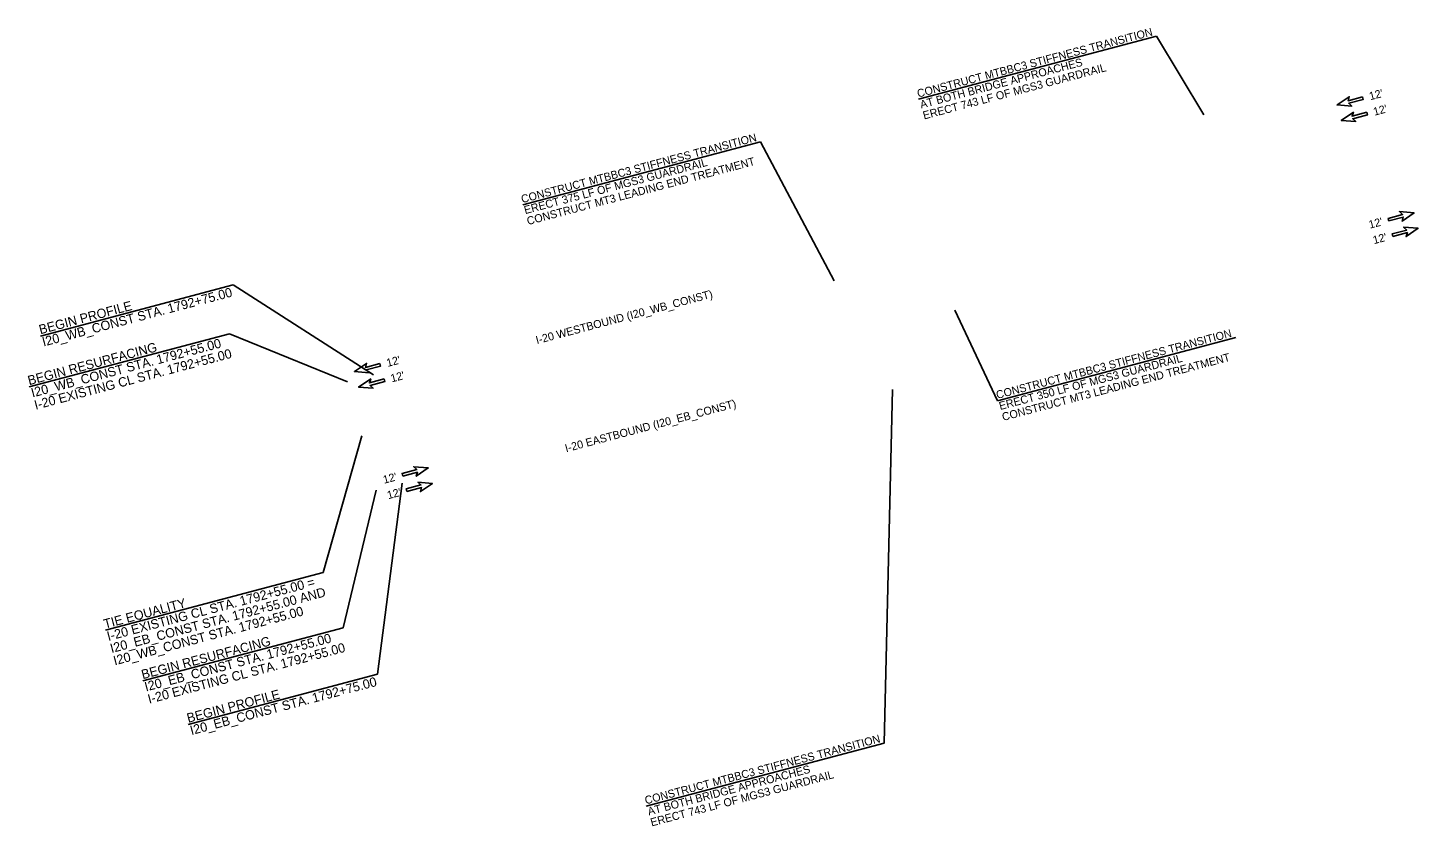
# Model space of a CAD drawing. Extents: x 2110155 to 2114862, y 866944 to 868497.
# Drawn here: x 2110155 to 2111197, y 866944 to 867543 of the extents above; entities that cross this region are included whole.
import ezdxf

# ---------------------------------------------------------------- set-up
doc = ezdxf.new("R2010")
doc.units = 0
doc.layers.add('RD_SHT_Bndy', color=7, linetype='Continuous')

msp = doc.modelspace()

# ---------------------------------------------------------------- linework, layer by layer
at = {"layer": 'RD_SHT_Bndy'}
for p, q in [((2111001.2, 867536.4), (2110822.8, 867489.1)), ((2110704.3, 867457.2), (2110525.9, 867409.9)), ((2110308.7, 867349.8), (2110164.2, 867311.5)), ((2110306, 867313.1), (2110155.8, 867273.3)), ((2111060.7, 867310.4), (2110882, 867263)), ((2110376.3, 867134.1), (2110213.1, 867090.8)), ((2110391.2, 867092.6), (2110241, 867052.8)), ((2110417.1, 867057.8), (2110275.1, 867020.1)), ((2110797, 867006.2), (2110618.6, 866959))]:
    msp.add_line(p, q, dxfattribs=at)
for points in [[(2111001.2, 867536.4), (2111036.6, 867477.4)], [(2110704.3, 867457.2), (2110759.4, 867352.8)], [(2110308.7, 867349.8), (2110413.9, 867282.4)], [(2110882, 867263), (2110849.9, 867331)], [(2110306, 867313.1), (2110394.5, 867277.2)], [(2110797, 867006.2), (2110803.2, 867271.4)], [(2110376.3, 867134.1), (2110405.3, 867236.6)], [(2110391.2, 867092.6), (2110416.1, 867196)], [(2110417.1, 867057.8), (2110435.4, 867201.2)]]:
    msp.add_lwpolyline(points, dxfattribs=at)
for points in [[(2111155.7, 867490.9), (2111156.2, 867489), (2111145.3, 867486.1), (2111147.6, 867483.9), (2111136.6, 867484.8), (2111145.7, 867491), (2111144.8, 867488)], [(2111158.8, 867479.3), (2111159.3, 867477.4), (2111148.4, 867474.5), (2111150.6, 867472.3), (2111139.7, 867473.2), (2111148.8, 867479.4), (2111147.8, 867476.4)], [(2111175.3, 867397.8), (2111174.8, 867399.7), (2111185.7, 867402.6), (2111183.4, 867404.8), (2111194.3, 867403.9), (2111185.3, 867397.7), (2111186.2, 867400.7)], [(2111178.3, 867386.2), (2111177.8, 867388.1), (2111188.8, 867391), (2111186.5, 867393.2), (2111197.4, 867392.3), (2111188.4, 867386.1), (2111189.3, 867389.1)], [(2110418.8, 867290.9), (2110419.3, 867289), (2110408.4, 867286.1), (2110410.7, 867283.9), (2110399.7, 867284.8), (2110408.8, 867291), (2110407.9, 867288)], [(2110421.9, 867279.3), (2110422.4, 867277.4), (2110411.4, 867274.5), (2110413.7, 867272.3), (2110402.8, 867273.2), (2110411.9, 867279.4), (2110410.9, 867276.4)], [(2110436.1, 867206.5), (2110435.5, 867208.5), (2110446.5, 867211.4), (2110444.2, 867213.5), (2110455.1, 867212.6), (2110446.1, 867206.4), (2110447, 867209.4)], [(2110439.1, 867194.9), (2110438.6, 867196.9), (2110449.6, 867199.8), (2110447.3, 867201.9), (2110458.2, 867201), (2110449.2, 867194.8), (2110450.1, 867197.8)]]:
    msp.add_lwpolyline(points, close=True, dxfattribs=at)

# ---------------------------------------------------------------- texts
for s, height, p in [('CONSTRUCT MTBBC3 STIFFNESS TRANSITION', 6, (2110822.5, 867490.3)), ('AT BOTH BRIDGE APPROACHES', 6, (2110824.7, 867482.1)), ('ERECT 743 LF OF MGS3 GUARDRAIL', 6, (2110826.9, 867473.9)), ("12'", 6, (2111161.5, 867488.3)), ("12'", 6, (2111164.6, 867476.7)), ('CONSTRUCT MTBBC3 STIFFNESS TRANSITION', 6, (2110525.6, 867411.1)), ('ERECT 375 LF OF MGS3 GUARDRAIL', 6, (2110527.8, 867402.9)), ('CONSTRUCT MT3 LEADING END TREATMENT', 6, (2110529.9, 867394.7)), ("12'", 6, (2111161.2, 867392)), ("12'", 6, (2111164.3, 867380.4)), ('I20_WB_CONST STA. 1792+75.00', 7, (2110166.6, 867303.6)), ('I-20 WESTBOUND (I20_WB_CONST)', 6, (2110536.6, 867305.4)), ('BEGIN PROFILE', 7, (2110164.2, 867312.8)), ('I20_WB_CONST STA. 1792+55.00', 7, (2110158.3, 867265.4)), ('CONSTRUCT MTBBC3 STIFFNESS TRANSITION', 6, (2110881.8, 867264.3)), ('BEGIN RESURFACING', 7, (2110155.8, 867274.6)), ('I-20 EXISTING CL STA. 1792+55.00', 7, (2110160.7, 867256.2)), ('CONSTRUCT MT3 LEADING END TREATMENT', 6, (2110886.2, 867247.8)), ("12'", 6, (2110424.6, 867288.3)), ('ERECT 350 LF OF MGS3 GUARDRAIL', 6, (2110884, 867256)), ("12'", 6, (2110427.7, 867276.7)), ('I-20 EASTBOUND (I20_EB_CONST)', 6, (2110558.5, 867224.3)), ("12'", 6, (2110422, 867200.7)), ("12'", 6, (2110425.1, 867189.1)), ('I-20 EXISTING CL STA. 1792+55.00 =', 7, (2110215.2, 867082.8)), ('I20_EB_CONST STA. 1792+55.00 AND', 7, (2110217.6, 867073.7)), ('TIE EQUALITY', 7, (2110212.7, 867092)), ('I20_WB_CONST STA. 1792+55.00', 7, (2110220, 867064.5)), ('BEGIN RESURFACING', 7, (2110241, 867054.1)), ('I20_EB_CONST STA. 1792+55.00', 7, (2110243.4, 867044.9)), ('I-20 EXISTING CL STA. 1792+55.00', 7, (2110245.8, 867035.7)), ('I20_EB_CONST STA. 1792+75.00', 7, (2110277.5, 867012.2)), ('BEGIN PROFILE', 7, (2110275.1, 867021.4)), ('CONSTRUCT MTBBC3 STIFFNESS TRANSITION', 6, (2110618.3, 866960.2)), ('AT BOTH BRIDGE APPROACHES', 6, (2110620.5, 866951.9)), ('ERECT 743 LF OF MGS3 GUARDRAIL', 6, (2110622.6, 866943.7))]:
    msp.add_text(s, height=height, rotation=14.8448, dxfattribs=at).set_placement(p)

doc.saveas('drawing.dxf')
